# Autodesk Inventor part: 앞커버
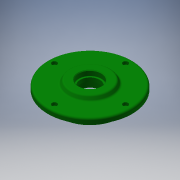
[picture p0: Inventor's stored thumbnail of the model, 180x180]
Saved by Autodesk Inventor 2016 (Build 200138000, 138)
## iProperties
Created: 2016-11
Part Number: 앞커버
Material: 알루미늄 6061
Document SubType Name: Modeling
Designer: mduedu
Density: 2.71 g/cm^3
Mass: 511.35 g
Surface Area: 365.029 cm^2
Volume: 188.69 cm^3
Appearance: 진녹색
Author: mduedu
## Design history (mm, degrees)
sketch "스케치1"
  geometry: L1 (28.5, -17.5)-(28.5, -30); L2 (28.5, -30)-(22.5, -33.464); L3 (22.5, -33.464)-(22.5, -65); L4 (22.5, -65)-(14.5, -65); L5 (14.5, -65)-(14.5, -47.5); L6 (14.5, -47.5)-(0, -47.5); L7 (0, -47.5)-(0, -23.5); L8 (0, 0)-(28.5, 0); L9 (14.5, -23.5)-(14.5, -15); L10 (14.5, -15)-(20.5, -15); L11 (20.5, -15)-(20.5, -17.5); L12 (0, -23.5)-(14.5, -23.5); L13 (20.5, -17.5)-(28.5, -17.5)
  constraints: 26 end point, 8 parallel, 3 perpendicular, 2 horizontal, 2 vertical alignment, 1 collinear
  dimensions: "d0" = 14.5 distance of L5.end L6.end; "d2" = 8 distance of L3.end L4.end; "d3" = 6 distance between parallel lines of L1 L3; "d4" = 120 deg angle of L3 L2; "d5" = 8 distance of L11.end L1.start; "d6" = 60 diameter of L1.end L8; "d7" = 30 diameter of L10 L8; "d8" = 47 diameter of L12 L8; "d9" = 35 diameter of L13 L8; "d10" = 95 diameter of L6 L8; "d11" = 130 diameter of L4 L8
revolve "회전1" sketch "스케치1" stored, may be unused: angle "d12" = 90 deg
fillet "모깎기1" dims "d13" = 0.5
fillet "모깎기2" dims "d14" = 3
chamfer "모따기1" distance "d15" = 1; stored, may be unused: second distance "d16" = 2, angle "d17" = 45 deg
fillet "모깎기3" dims "d18" = 0.3
sketch "스케치2" dims "d19" = 110
  geometry: 6 further points
  constraints: 2 vertical alignment, 1 coincident, 7 other
  dimensions: "d22" = 360 deg dimension on point (0, 0) point (0, 55) (derived)
sketch "스케치3"
  geometry: 4 further points
  constraints: 4 other
hole "구멍1" sketch "스케치3" at (0, 55), (-55, 0), (55, 0), (0, -55) diameter "d24" = 4.5; stored, may be unused: countersink angle "d28" = 90 deg, drill point angle "d30" = 0 deg; dims "d25" = 6, "d26" = 8, "d27" = 4.6, "d29" = 8
node "솔리드1"
